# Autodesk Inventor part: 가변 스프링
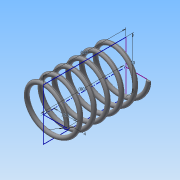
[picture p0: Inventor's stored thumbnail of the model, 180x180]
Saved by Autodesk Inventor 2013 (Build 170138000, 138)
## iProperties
Created: 2018-06
Part Number: 가변 스프링
Material: 일반
Document SubType Name: Modeling
Designer: Administrator
Density: 1 g/cm^3
Author: Administrator
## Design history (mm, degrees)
sketch "스케치1"
  geometry: L1 (0, 0)-(0, 80); L2 (0, 0)-(22.5, 0); L3 (0, 80)-(20.5, 80); C1 r 2 at (22.5, 0)
  constraints: 6 end point, 1 centre point, 1 coincident, 1 parallel, 1 perpendicular, 1 vertical
  dimensions: "d0" = 80 distance of L1.start L1.end (derived); "d1" = 22.5 distance of L1.start L2.end; "d2" = 4 diameter of C1
feature "코일1" sketch "스케치1" pitch "d3" = 10; turns "d5" = 6; dims "d4" = 80 (= d0), "d6" = 0, angle "d7" = 90 deg, angle "d8" = 90 deg, "d9" = 0, "d10" = 0
sketch "스케치2"
  geometry: L1 (0, -25)-(80, -25); L2 (80, -25)-(80, 25); L3 (80, 25)-(0, 25); L4 (0, 25)-(0, -25); 2 further points
  constraints: 8 end point, 2 coincident, 2 parallel, 1 horizontal, 1 midpoint, 1 perpendicular
  dimensions: "d11" = 80 distance of L3.end L2.end (derived); "d12" = 50 distance of L2.end L1.end
extrude "돌출1" sketch "스케치2" stored distance "d13" = 0; taper "d14" = 0 deg
node "솔리드1"
